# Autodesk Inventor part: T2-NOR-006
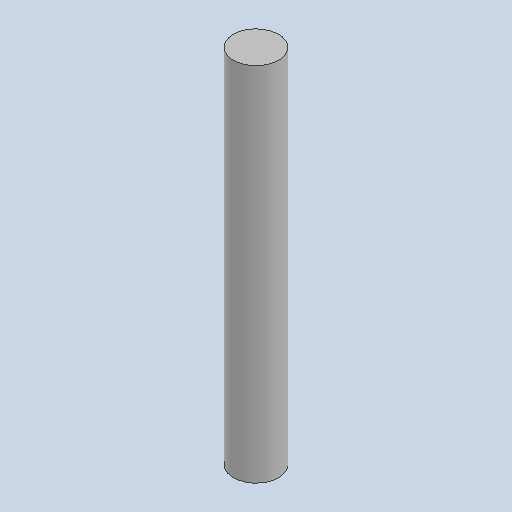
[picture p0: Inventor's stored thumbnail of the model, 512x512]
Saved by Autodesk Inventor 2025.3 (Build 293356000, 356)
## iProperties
Created: 2026-10
Part Number: T2-NOR-006
Material: Genérico
Document SubType Name: Modeling
Designer: Luis MuÃ±oz
Density: 1 g/cm^3
Appearance: Valor por defecto
Project: TESIS 2 - Plataforma mecatrÃ³nica preventiva desacoplada
Description: Pasador cilíndrico Ø3 × 24 mm
Author: Luis M
Title: Pasador cilÃ­ndrico Ã˜3 Ã— 24 mm
Revision Number: 00
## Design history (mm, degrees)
sketch "Boceto1"
  geometry: C1 r 1.5 at (0, 0); 1 further point
  constraints: 1 centre point, 1 coincident
  dimensions: "d0" = 3 diameter of C1
extrude "Extrusión1" new body sketch "Boceto1" distance "d1" = 24; taper "d2" = 0 deg
node "Sólido1"
